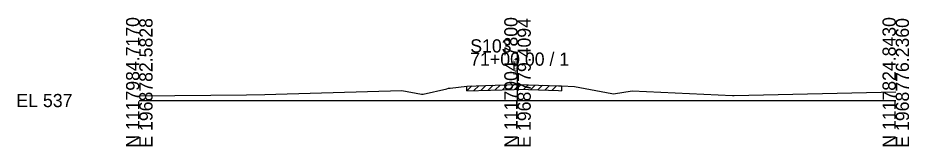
# Model space of a CAD drawing. Extents: x -26 to 163, y -10 to 45020.
# Drawn here: x -25.7 to 162.8, y 29990.3 to 30017.5 of the extents above; entities that cross this region are included whole.
import ezdxf

# ---------------------------------------------------------------- set-up
doc = ezdxf.new("R2010")
doc.units = 0
for name, color, linetype in [('RD_GPK_XS_Cell', 7, 'Continuous'), ('RD_XS_ExGround', 7, 'Continuous'), ('RD_XS_ExPaveRet', 7, 'Continuous'), ('RD_XS_TX_Elev_EX', 7, 'Continuous')]:
    doc.layers.add(name, color=color, linetype=linetype)

msp = doc.modelspace()

# ---------------------------------------------------------------- linework, layer by layer
at = {"layer": 'RD_GPK_XS_Cell'}
for p, q in [((80, 30000), (80, 30010.18)), ((0, 30000), (80, 30000)), ((80, 30000), (160, 30000))]:
    msp.add_line(p, q, dxfattribs=at)
at = {"layer": 'RD_XS_ExGround'}
for p, q in [((69.29, 30003.06), (79.31, 30003.37)), ((79.31, 30003.37), (80.18, 30003.39)), ((80.18, 30003.39), (88.69, 30003.1)), ((88.69, 30003.1), (89.32, 30003.08)), ((89.32, 30003.08), (92.02, 30002.98)), ((0, 30001), (22.71, 30001.22)), ((22.71, 30001.22), (26.54, 30001.29)), ((26.54, 30001.29), (28.9, 30001.35)), ((28.9, 30001.35), (55.55, 30002.09)), ((55.55, 30002.09), (59.7, 30001.38)), ((59.7, 30001.38), (60.06, 30001.32)), ((60.06, 30001.32), (65.04, 30002.5)), ((65.04, 30002.5), (65.42, 30002.6)), ((65.42, 30002.6), (65.75, 30002.64)), ((65.75, 30002.64), (69.29, 30003.06)), ((92.02, 30002.98), (99.92, 30001.49)), ((99.92, 30001.49), (100.29, 30001.42)), ((100.29, 30001.42), (104.23, 30002.05)), ((104.23, 30002.05), (125.47, 30001.05)), ((125.84, 30001.04), (160, 30001.85)), ((125.47, 30001.05), (125.84, 30001.04))]:
    msp.add_line(p, q, dxfattribs=at)
at = {"layer": 'RD_XS_ExPaveRet'}
for p, q in [((69.29, 30002.06), (70.32, 30003.1)), ((70.79, 30002.11), (71.82, 30003.14)), ((72.29, 30002.16), (73.32, 30003.19)), ((73.79, 30002.2), (74.82, 30003.23)), ((75.29, 30002.25), (76.32, 30003.28)), ((76.79, 30002.29), (77.82, 30003.32)), ((78.29, 30002.34), (79.32, 30003.37)), ((79.79, 30002.38), (80.78, 30003.37)), ((81.29, 30002.36), (82.26, 30003.32)), ((82.79, 30002.3), (83.76, 30003.27)), ((84.29, 30002.25), (85.26, 30003.22)), ((85.79, 30002.2), (86.76, 30003.17)), ((87.29, 30002.15), (88.26, 30003.12)), ((89.32, 30003.08), (89.32, 30002.08)), ((69.29, 30002.06), (69.29, 30003.06)), ((69.29, 30002.06), (79.31, 30002.37)), ((79.31, 30002.37), (80.18, 30002.39)), ((80.18, 30002.39), (88.69, 30002.1)), ((88.69, 30002.1), (89.32, 30002.08))]:
    msp.add_line(p, q, dxfattribs=at)

# ---------------------------------------------------------------- texts
at = {"layer": 'RD_GPK_XS_Cell'}
for s, p in [('N 1117984.7170', (0, 29990)), ('E 1968782.5828', (2.8, 29990)), ('N 1117904.7800', (80, 29990)), ('E 1968779.4094', (82.8, 29990)), ('N 1117824.8430', (160, 29990)), ('E 1968776.2360', (162.8, 29990))]:
    msp.add_text(s, height=2.8, rotation=90, dxfattribs=at).set_placement(p)
for s, p in [('S103', (70, 30010.18)), ('71+00.00 / 1', (70, 30007.38)), ('EL 537', (-26, 29998.6))]:
    msp.add_text(s, height=2.8, dxfattribs=at).set_placement(p)
at = {"layer": 'RD_XS_TX_Elev_EX'}
msp.add_text('540.39', height=0.8, rotation=90, dxfattribs=at).set_placement((79.9, 30005.39))

doc.saveas('drawing.dxf')
